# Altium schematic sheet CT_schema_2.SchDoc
size 276 x 169 mm
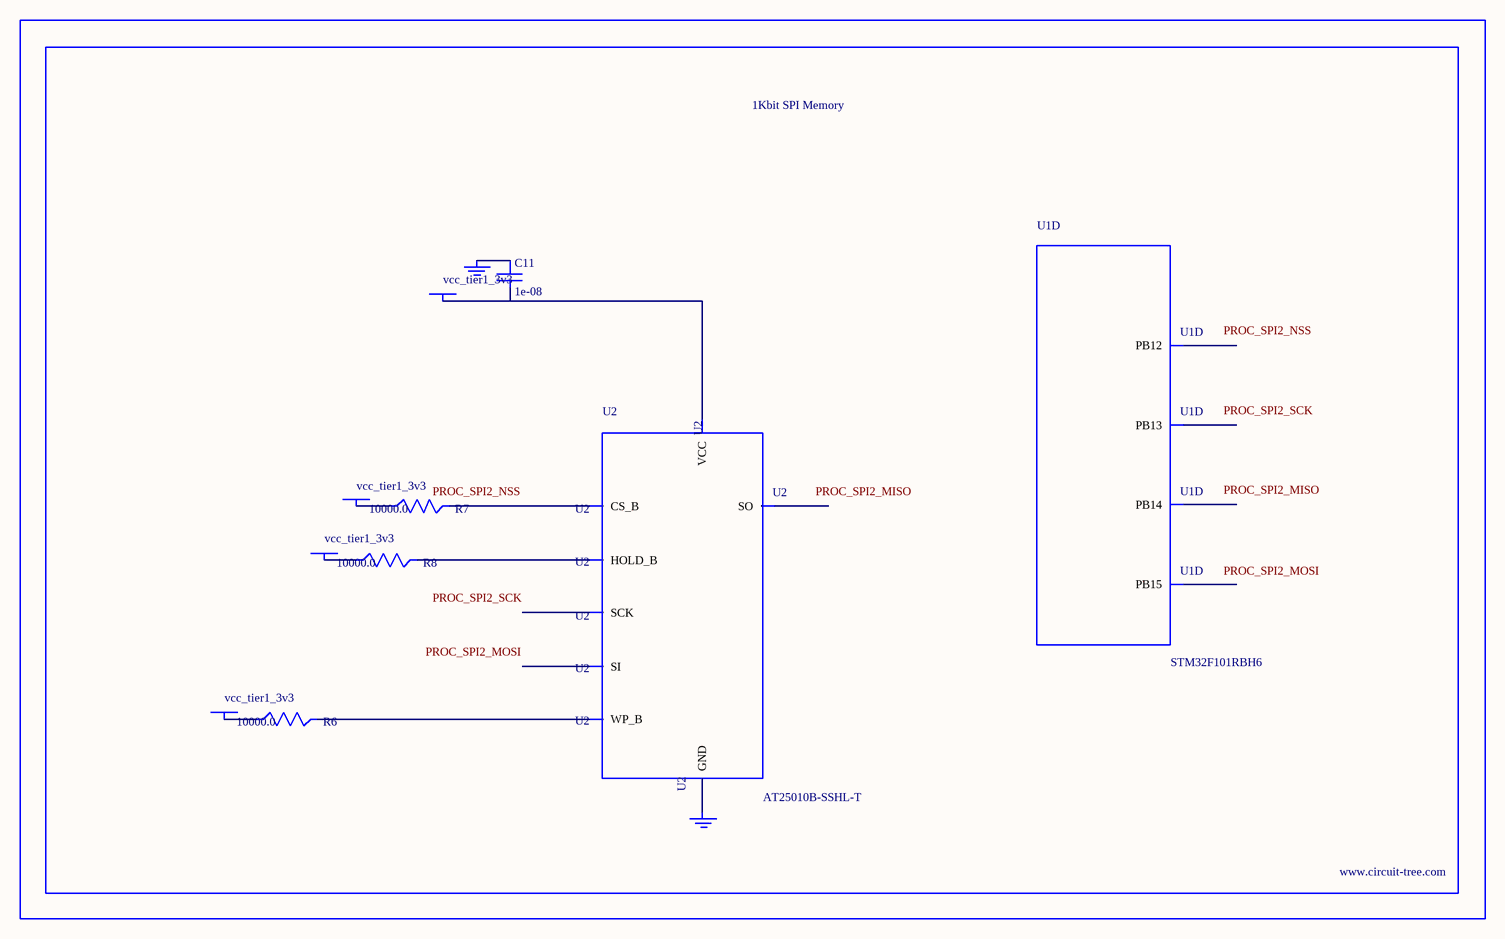
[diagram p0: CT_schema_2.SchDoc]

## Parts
BORDER1  (no value)
C11  1e-08  [C0402]
GND_INSTANCE_1_0  (no value)
GND_INSTANCE_1_1  (no value)
POWER_INSTANCE_1_0  vcc_tier1_3v3
POWER_INSTANCE_1_1  vcc_tier1_3v3
POWER_INSTANCE_1_2  vcc_tier1_3v3
POWER_INSTANCE_1_3  vcc_tier1_3v3
R6  10000.0  [R0603]
R7  10000.0  [R0603]
R8  10000.0  [R0603]
U1  STM32F101RBH6  [TFBGA64]  (part D of 7)
U2  AT25010B-SSHL-T  [SOIC-8]

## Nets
NetC11_1: C11.1 GND_INSTANCE_1_0.0(GND)
NetC11_2: C11.2 POWER_INSTANCE_1_3.0(PWR) U2.8(VCC)
NetGND_INSTANCE_1_1_0: GND_INSTANCE_1_1.0(GND) U2.4(GND)
NetPOWER_INSTANCE_1_0_0: POWER_INSTANCE_1_0.0(PWR) R7.1
NetPOWER_INSTANCE_1_1_0: POWER_INSTANCE_1_1.0(PWR) R6.1
NetPOWER_INSTANCE_1_2_0: POWER_INSTANCE_1_2.0(PWR) R8.1
NetR6_2: R6.2 U2.3(WP_B)
NetR7_2: R7.2 U2.1(CS_B)
NetR8_2: R8.2 U2.7(HOLD_B)

Not connected (* = marked no-connect by the designer): U1 F7(PB15) F8(PB14) G8(PB13) H8(PB12); U2 2(SO) 5(SI) 6(SCK)

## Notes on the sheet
- Labels drawn without touching a wire or pin: PROC_SPI2_MISO, PROC_SPI2_MOSI, PROC_SPI2_NSS, PROC_SPI2_SCK

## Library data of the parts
BORDER1 = BORDER_PAGE1
C11 = C0402C103K3RAC
GND_INSTANCE_1_0 GND_INSTANCE_1_1 = GND
POWER_INSTANCE_1_0-POWER_INSTANCE_1_3 = PWR
R6-R8 = RC0603JR-0710KL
